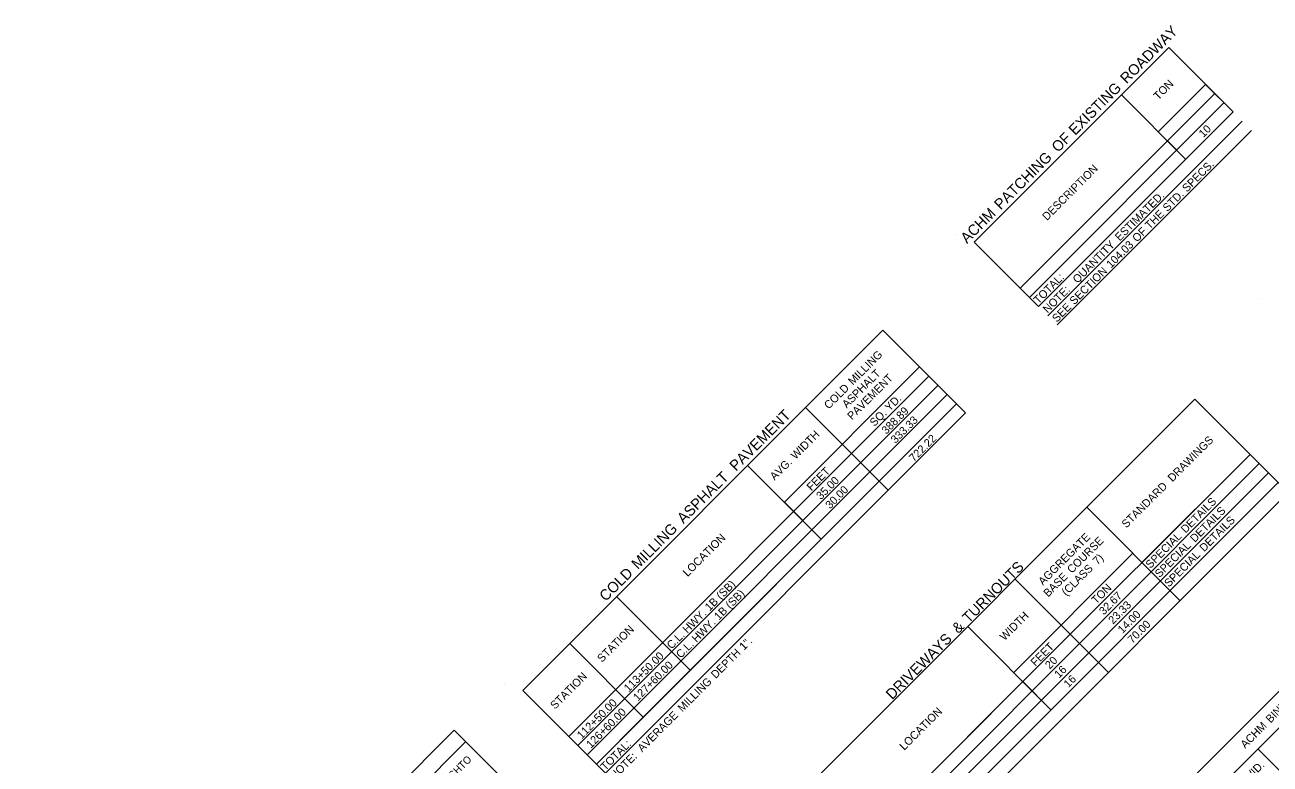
# Model space of a CAD drawing. Extents: x 1675667 to 1681231, y 227227 to 232694.
# Drawn here: x 1678206 to 1679139, y 230621 to 231175 of the extents above; entities that cross this region are included whole.
import ezdxf

# ---------------------------------------------------------------- set-up
doc = ezdxf.new("R2010")
doc.units = 0
doc.layers.add('Default', color=7, linetype='Continuous')

msp = doc.modelspace()

# ---------------------------------------------------------------- linework, layer by layer
at = {"layer": 'Default'}
for p, q in [((1678917.61, 231012.14), (1679063.4, 231157.97)), ((1679111.67, 231109.72), (1679063.4, 231157.97)), ((1679055.48, 231094.89), (1679090.99, 231130.4)), ((1679111.67, 231109.72), (1679090.99, 231130.4)), ((1678952.08, 230977.68), (1679097.88, 231123.51)), ((1679076.17, 231074.21), (1679027.9, 231122.46)), ((1678958.98, 230970.78), (1679104.78, 231116.61)), ((1678965.87, 230963.89), (1679111.67, 231109.72)), ((1678972.77, 230957), (1679118.57, 231102.83)), ((1678979.66, 230950.1), (1679125.46, 231095.93)), ((1679076.17, 231074.21), (1679062.38, 231088)), ((1678525.01, 230054.56), (1679538.35, 231068.14)), ((1678778.69, 230280.72), (1679552.14, 231054.36)), ((1678903.82, 231017.66), (1678903.82, 231017.66)), ((1678965.87, 230963.89), (1678917.61, 231012.14)), ((1678965.87, 230963.89), (1678917.61, 231012.14)), ((1679132.61, 230969.97), (1679132.61, 230969.97)), ((1678579.16, 230676.22), (1678849.04, 230946.17)), ((1678911.09, 230884.12), (1678849.04, 230946.17)), ((1678911.09, 230884.12), (1678849.04, 230946.17)), ((1678775.28, 230817.23), (1678876.62, 230918.59)), ((1678613.64, 230641.75), (1678883.51, 230911.7)), ((1678620.53, 230634.86), (1678890.41, 230904.81)), ((1678627.43, 230627.97), (1678897.3, 230897.91)), ((1678634.32, 230621.07), (1678904.2, 230891.02)), ((1678731.42, 230542.8), (1679082.99, 230894.46)), ((1678853.19, 230826.21), (1678791.13, 230888.25)), ((1678846.29, 230833.1), (1678904.2, 230891.02)), ((1679152.98, 230824.49), (1679082.99, 230894.46)), ((1679152.98, 230824.49), (1679082.99, 230894.46)), ((1678641.22, 230614.18), (1678911.09, 230884.12)), ((1678846.29, 230833.1), (1678825.61, 230853.78)), ((1678954.09, 230682.79), (1679124.36, 230853.1)), ((1679043.36, 230772.08), (1679124.36, 230853.1)), ((1678802.87, 230789.66), (1678747.7, 230844.81)), ((1678779.69, 230494.55), (1679131.26, 230846.2)), ((1678786.58, 230487.66), (1679138.15, 230839.31)), ((1678793.82, 230480.42), (1679145.39, 230832.07)), ((1678801.41, 230472.84), (1679152.98, 230824.49)), ((1678802.87, 230789.66), (1678775.28, 230817.23)), ((1679071.98, 230743.47), (1679001.99, 230813.44)), ((1678704.63, 230691.4), (1678802.87, 230789.66)), ((1678947.2, 230689.68), (1679036.47, 230778.97)), ((1679018.21, 230689.69), (1678948.22, 230759.66)), ((1678704.63, 230691.4), (1678649.47, 230746.55)), ((1678772.79, 230501.44), (1678989.59, 230718.3)), ((1678975.12, 230661.76), (1678912.72, 230724.15)), ((1678989.59, 230718.3), (1678982.7, 230725.19)), ((1678669.48, 230656.24), (1678614.32, 230711.39)), ((1678704.63, 230691.4), (1678683.95, 230712.08)), ((1678669.48, 230656.24), (1678704.63, 230691.4)), ((1679018.21, 230689.69), (1679010.62, 230697.27)), ((1678565.37, 230681.73), (1678565.37, 230681.73)), ((1678772.79, 230501.44), (1678954.09, 230682.79)), ((1678975.12, 230661.76), (1678954.09, 230682.79)), ((1678641.22, 230614.18), (1678579.16, 230676.22)), ((1678641.22, 230614.18), (1678579.16, 230676.22)), ((1678669.48, 230656.24), (1678648.79, 230676.92)), ((1678634.32, 230621.07), (1678669.48, 230656.24)), ((1678205.92, 230324.54), (1678527.85, 230646.54)), ((1678667.47, 230506.95), (1678527.85, 230646.54)), ((1678214.54, 230315.92), (1678536.47, 230637.93)), ((1679150.95, 230611.7), (1679130.26, 230632.38))]:
    msp.add_line(p, q, dxfattribs=at)

# ---------------------------------------------------------------- texts
for s, height, p in [(' ROADWAY', 8, (1679029.71, 231128.26)), (' EXISTING', 8, (1678991.1, 231089.65)), ('TON', 6, (1679055.55, 231118.29)), (' OF', 8, (1678978.3, 231076.84)), ('10', 6, (1679089.44, 231090.14)), (' PATCHING', 8, (1678935.31, 231033.84)), ('DESCRIPTION', 6, (1678972.1, 231027.93)), (' SPECS.', 6, (1679075.48, 231047.64)), (' ESTIMATED.', 6, (1679025.07, 231011)), (' STD.', 6, (1679060.85, 231033)), ('ACHM', 8, (1678912.16, 231010.69)), (' THE', 6, (1679047.66, 231019.81)), (' OF', 6, (1679038.06, 231010.21)), ('   QUANTITY', 6, (1678990.21, 230976.13)), (' 104.03', 6, (1679018.56, 230990.7)), (' SECTION', 6, (1678991.05, 230963.19)), ('TOTAL:', 6, (1678965.71, 230965.43)), ('NOTE:', 6, (1678972.61, 230958.53)), ('SEE', 6, (1678979.51, 230951.64)), (' MILLING', 6, (1678825.06, 230903.09)), ('ASPHALT', 6, (1678822.06, 230887.36)), ('COLD', 6, (1678808.56, 230886.58)), ('PAVEMENT', 6, (1678825.95, 230878.52)), (' YD.', 6, (1678852.58, 230883.41)), (' PAVEMENT', 8, (1678736.9, 230838)), ('388.89', 6, (1678851.68, 230867.76)), ('SQ.', 6, (1678842.77, 230873.6)), ('333.33', 6, (1678858.58, 230860.87)), (' WIDTH', 6, (1678782.07, 230847.35)), ('722.22', 6, (1678872.38, 230847.1)), (' DRAWINGS', 6, (1679064.64, 230830.49)), (' ASPHALT', 8, (1678697.55, 230798.64)), ('AVG.', 6, (1678767.98, 230833.27)), ('FEET', 6, (1678795.53, 230825.39)), ('35.00', 6, (1678802.67, 230818.74)), ('STANDARD', 6, (1679031.67, 230797.51)), ('30.00', 6, (1678809.57, 230811.85)), (' DETAILS', 6, (1679074.45, 230792.03)), (' DETAILS', 6, (1679081.34, 230785.14)), (' DETAILS', 6, (1679088.41, 230778.07)), (' MILLING', 8, (1678663.35, 230764.43)), ('LOCATION', 6, (1678702.71, 230761.08)), ('AGGREGATE', 6, (1678969.15, 230754.6)), ('SPECIAL', 6, (1679049.62, 230767.2)), (' COURSE', 6, (1678989.2, 230761.92)), ('SPECIAL', 6, (1679056.52, 230760.31)), (' 7)', 6, (1679008.41, 230768.41)), ('SPECIAL', 6, (1679063.58, 230753.24)), ('COLD', 8, (1678641.35, 230742.42)), (' TURNOUTS', 8, (1678911.36, 230724.02)), ('BASE', 6, (1678973.02, 230745.74)), ('(CLASS', 6, (1678986.64, 230746.64)), (' (SB)', 6, (1678726.22, 230742.27)), ('TON', 6, (1679009.13, 230740.49)), (' 1B', 6, (1678717.64, 230733.69)), (' (SB)', 6, (1678733.11, 230735.38)), ('32.67', 6, (1679014.77, 230732.34)), (' 1B', 6, (1678724.53, 230726.8)), ('23.33', 6, (1679021.66, 230725.45)), (' HWY.', 6, (1678701.03, 230717.08)), (' HWY.', 6, (1678707.93, 230710.19)), (' &', 8, (1678903.58, 230716.24)), ('WIDTH', 6, (1678940.35, 230713.06)), ('14.00', 6, (1679028.74, 230718.39)), ('70.00', 6, (1679036.16, 230710.98)), ('STATION', 6, (1678638.48, 230696.84)), ('DRIVEWAYS', 8, (1678856.1, 230668.75)), ('C.L.', 6, (1678690.68, 230706.73)), ('C.L.', 6, (1678697.58, 230699.84)), (' 1".', 6, (1678743.43, 230704.32)), ('FEET', 6, (1678963.48, 230693.87)), ('113+50.00', 6, (1678658.47, 230674.51)), (' DEPTH', 6, (1678722.17, 230683.06)), ('20', 6, (1678974.26, 230691.82)), ('STATION', 6, (1678603.33, 230661.68)), ('127+60.00', 6, (1678665.37, 230667.62)), ('16', 6, (1678981.15, 230684.92)), (' MILLING', 6, (1678697.19, 230658.07)), ('16', 6, (1678988.21, 230677.85)), (' BINDER', 6, (1679138.1, 230649.76)), ('112+50.00', 6, (1678623.32, 230639.35)), ('126+60.00', 6, (1678630.21, 230632.45)), ('LOCATION', 6, (1678865.14, 230630.94)), ('  AVERAGE', 6, (1678665.55, 230626.42)), ('ACHM', 6, (1679120.74, 230632.4)), ('TOTAL:', 6, (1678641.06, 230615.72)), ('AASHTO', 5.5, (1678519.93, 230602.65)), ('NOTE:', 6, (1678647.95, 230608.82)), (' WID.', 6, (1679121.54, 230605.62))]:
    msp.add_text(s, height=height, rotation=45.00703, dxfattribs=at).set_placement(p)

doc.saveas('drawing.dxf')
